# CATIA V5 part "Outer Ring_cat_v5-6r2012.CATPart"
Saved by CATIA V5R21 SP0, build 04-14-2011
Part number: Outer Ring
Bounding box of the stored display mesh (mm): x -99.819 to 99.819, y 0 to 50, z -100 to 100
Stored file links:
  D:\CATIA V5R21 E-RESOURCES\CATIA-V5R21\catia-v5r21-Tut\c16-catia-v5r21-tut\c16-catia-v5r21-tut04\Outer Ring_cat_v5r21.CATPart
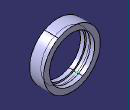
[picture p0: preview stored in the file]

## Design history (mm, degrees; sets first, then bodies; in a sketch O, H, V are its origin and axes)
Body1 (main body)
  Sketch1 on yz-plane, origin (0, 0, 0), H (0, 1, 0), V (0, 0, 1)
    point P1 (0, 80)
    line L1 (0, 80) -> (0, 100)
    line L2 (0, 100) -> (50, 100)
    line L3 (50, 100) -> (50, 80)
    line L4 (50, 80) -> (35, 80)
    line L5 (35, 80) -> (35, 85)
    line L6 (35, 85) -> (15, 85)
    line L7 (15, 85) -> (15, 80)
    point P8 (15, 80)
    line L8 (15, 80) -> (0, 80)
    point P9 (0, 80)
    distance H L8 = 80
    length L2 = 50
    length L5 = 5
    length L8 = 15
    length L4 = 15
    length L1 = 20
    coincidence: P1 V, P8 L4, P9 V, P9 P1
    vertical: L1 V, L3 V, L5 V, L7 V
    horizontal: L2 H, L4 H, L6 H, L8 H
  Shaft1: profile Sketch1, axis Sketch1.H, angle 360
  Plane1: type Offset, RefPlane face of Shaft1 from Sketch1.L5, Offset 10, reversed
  Sketch2 on Plane1, origin (0, 25, 0), H (-1, 0, 0), V (0, 0, 1)
    projected circle E1 centre (0, 0) radius 85 from edge [face of Shaft1 from Sketch1.L6 | face of Shaft1 from Sketch1.L7]
  Point1: type OnCurve, Support Sketch2, RefPoint {extremum Reference Sketch2, Direction (1, 2, 3)}, Length 282.187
